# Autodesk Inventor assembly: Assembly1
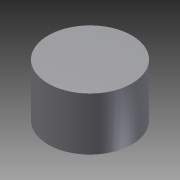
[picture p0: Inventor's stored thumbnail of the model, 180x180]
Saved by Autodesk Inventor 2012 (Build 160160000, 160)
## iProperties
Created: 2018-05
Part Number: Assembly1
Document SubType Name: Assembly
Designer: Elkawokgy
Author: Elkawokgy
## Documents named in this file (2)
- C:\Users\Elkawokgy\Downloads\New folder\Assembly1.iam
- C:\Users\Elkawokgy\Downloads\New folder\Part1.ipt
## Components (1 placed, 1 different names)
1. Part1:1
